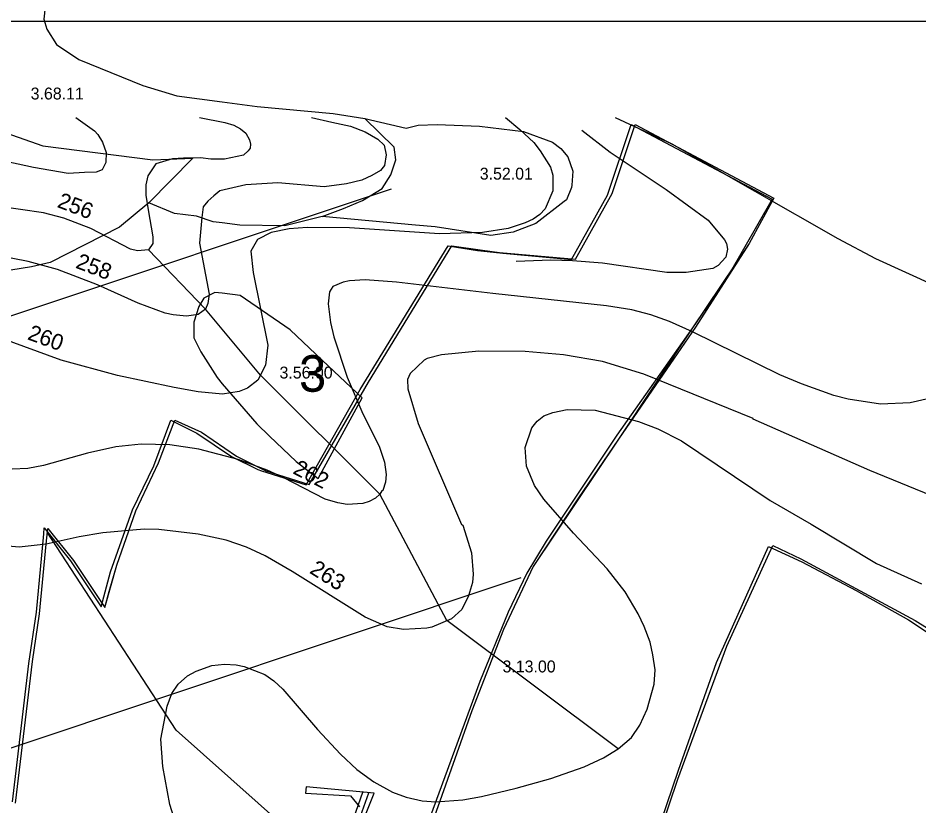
# Model space of a CAD drawing. Extents: x -662500 to -653478, y -1056827 to -1049993.
# Drawn here: x -660129 to -659561, y -1051447 to -1050951 of the extents above; entities that cross this region are included whole.
import ezdxf

# ---------------------------------------------------------------- set-up
doc = ezdxf.new("R2010")
doc.units = 0
for name, color, linetype in [('58', 7, 'Continuous'), ('Vrstva 1', 7, 'Continuous'), ('Vrstva 12', 7, 'Continuous'), ('Vrstva 15', 7, 'Continuous'), ('Vrstva 24', 7, 'Continuous'), ('Vrstva 46', 7, 'Continuous'), ('Vrstva 47', 7, 'Continuous'), ('Vrstva 5', 7, 'Continuous'), ('Vrstva 57', 7, 'Continuous'), ('Vrstva 61', 7, 'Continuous'), ('Vrstva 7', 7, 'Continuous'), ('Vrstva 9', 7, 'Continuous')]:
    doc.layers.add(name, color=color, linetype=linetype)

msp = doc.modelspace()

# ---------------------------------------------------------------- linework, layer by layer
at = {"layer": '58'}
for points in [[(-660132.24, -1051444.58), (-660121.99, -1051357.39), (-660117.08, -1051324.93), (-660112.54, -1051275.65), (-660112.18, -1051271.81), (-660095.7, -1051292.7), (-660076.32, -1051321.57), (-660070.35, -1051299.6), (-660056.66, -1051260.6), (-660043.22, -1051232.73), (-660032.52, -1051204.03), (-660015.99, -1051212.13), (-659994.21, -1051226.93), (-659977.64, -1051235.19), (-659975.32, -1051235.92), (-659947.13, -1051244.87), (-659913.18, -1051184.68), (-659857.71, -1051094.13), (-659839.05, -1051097.05), (-659823.12, -1051098.76), (-659779.88, -1051102.74), (-659757.26, -1051062.21), (-659742.38, -1051017.87), (-659695.85, -1051042.42), (-659653.55, -1051064.75), (-659680.53, -1051112.07), (-659703.59, -1051145.9), (-659751.4, -1051213.59), (-659795.85, -1051280.28), (-659808.05, -1051300.49), (-659819.9, -1051325.04), (-659837.72, -1051368.71), (-659869.54, -1051455.64)], [(-659759.05, -1051561.67), (-659712.51, -1051424.5), (-659688.44, -1051356.77), (-659655.81, -1051283.68), (-659634.82, -1051293.28), (-659600.6, -1051311.32), (-659567.44, -1051329.85), (-659545.76, -1051344.32), (-659531.38, -1051355.46), (-659520.03, -1051370.23), (-659502.95, -1051403.94), (-659485.94, -1051436.16), (-659472.84, -1051453.09)]]:
    msp.add_lwpolyline(points, dxfattribs=at)
at = {"layer": 'Vrstva 1'}
for points in [[(-660130.33, -1051445.37), (-660119.59, -1051356), (-660115.2, -1051326.09), (-660111.07, -1051282.11), (-660109.84, -1051272.31), (-660093.66, -1051292.38), (-660074.1, -1051322.03), (-660071.2, -1051311.9), (-660066.47, -1051295.41), (-660054.39, -1051261.14), (-660040.25, -1051230.96), (-660029.86, -1051204.12), (-660013.02, -1051211.57), (-659991.09, -1051226.64), (-659972.65, -1051235.92), (-659945.31, -1051244.62), (-659907.77, -1051180.02), (-659855.25, -1051094.11), (-659835.96, -1051096.88), (-659825.34, -1051098.5), (-659777.47, -1051102.56), (-659754.32, -1051061.32), (-659739.86, -1051017.86), (-659652.45, -1051064.24)], [(-659652.45, -1051064.24), (-659668.02, -1051092.7), (-659701.79, -1051145.35), (-659750.22, -1051216.02), (-659775.49, -1051252.9), (-659804.11, -1051296.33), (-659822.86, -1051335.88), (-659842.66, -1051387.23), (-659885.47, -1051507.41)], [(-659757.26, -1051561.49), (-659712.92, -1051430.24), (-659682.02, -1051346.44), (-659653.09, -1051282.92), (-659635.47, -1051291.43), (-659563.33, -1051330.24), (-659543.44, -1051342.71), (-659530.33, -1051353.77), (-659518.69, -1051369.3), (-659481.35, -1051440), (-659464.55, -1051461.63)]]:
    msp.add_lwpolyline(points, dxfattribs=at)
at = {"layer": 'Vrstva 12'}
msp.add_lwpolyline([(-660048.46, -1051908.46), (-660047.42, -1051899.64), (-660032.86, -1051840.77), (-660015.78, -1051767.82), (-659988.42, -1051674.38), (-659968.73, -1051615.68), (-659955.2, -1051573.56), (-659924.48, -1051485.89), (-659907.54, -1051438.82)], dxfattribs=at)
at = {"layer": 'Vrstva 15'}
msp.add_lwpolyline([(-659562.5, -1051644.38), (-659615.17, -1051617.96), (-659839.2, -1051534.06), (-659887.53, -1051509.79), (-659927, -1051486.15), (-659960.24, -1051460.73), (-660029.15, -1051399.28), (-660110.36, -1051274.6)], dxfattribs=at)
at = {"layer": 'Vrstva 24'}
for points in [[(-660087.8, -1050870.78), (-660098.95, -1050896.66), (-660106.11, -1050926.12), (-660111.62, -1050943.74), (-660112.44, -1050951.45), (-660110.52, -1050957.79), (-660104.46, -1050967.42), (-660090.42, -1050976.78), (-660050.08, -1050993.3), (-660028.6, -1050999.64), (-660000, -1051003.52), (-659977.94, -1051006.52), (-659930.03, -1051010.93), (-659910.06, -1051013.96)], [(-660219.08, -1051033.89), (-660211.53, -1051026.06), (-660187.02, -1051017.8), (-660160.45, -1051014.5), (-660148.34, -1051016.15), (-660136.5, -1051023.04), (-660113.09, -1051031.3), (-660043.71, -1051040.11), (-660018.65, -1051039.01), (-660046.3, -1051067.21)], [(-659937.05, -1051075.63), (-659923.56, -1051070.68), (-659911.72, -1051065.72), (-659899.33, -1051058.01), (-659893.82, -1051049.48), (-659890.52, -1051040.11), (-659891.62, -1051032.13), (-659910.06, -1051013.96)], [(-659910.06, -1051013.96), (-659884.18, -1051020.01), (-659876.47, -1051018.09), (-659864.63, -1051017.81), (-659837.92, -1051018.91), (-659810.11, -1051022.22), (-659791.94, -1051028.82), (-659786.71, -1051032.95), (-659782.3, -1051038.19), (-659779, -1051047.27), (-659779.7, -1051055.94), (-659779.83, -1051057.46), (-659783.13, -1051065.17), (-659784.51, -1051066.24), (-659802.4, -1051080.04), (-659813.99, -1051084.49), (-659816.72, -1051085.55), (-659830.76, -1051087.75), (-659865.73, -1051082.24), (-659878.14, -1051081.09), (-659937.05, -1051075.63)], [(-660046.3, -1051067.21), (-660064.75, -1051082.36), (-660108.39, -1051104.66), (-660120.23, -1051107.41), (-660153, -1051112.64), (-660174.75, -1051114.57), (-660185.22, -1051114.3), (-660198.16, -1051112.92), (-660298.25, -1051096.4), (-660311.46, -1051099.15), (-660354.83, -1051095.85), (-660390.35, -1051091.17), (-660414.86, -1051087.04), (-660442.11, -1051080.15)], [(-659937.05, -1051075.63), (-659960.67, -1051081.53), (-659989.03, -1051081.25), (-660000, -1051079.82), (-660005.83, -1051079.05), (-660016.29, -1051075.47), (-660030.06, -1051073.82), (-660046.3, -1051067.21)]]:
    msp.add_lwpolyline(points, dxfattribs=at)
msp.add_lwpolyline([(-659932.99, -1051170.05), (-659957.29, -1051147.22), (-659988.68, -1051125.47), (-660000, -1051124.1), (-660004.65, -1051123.54), (-660011.53, -1051127.12), (-660014.83, -1051132.36), (-660017.86, -1051142.27), (-660017.86, -1051152.18), (-660013.46, -1051160.99), (-660003.27, -1051177.24), (-660000, -1051181.05), (-659978.21, -1051206.42), (-659970.15, -1051214.13), (-659953.43, -1051230.1), (-659939.66, -1051240.84), (-659911.85, -1051189.9)], close=True, dxfattribs=at)
at = {"layer": 'Vrstva 46'}
msp.add_line((-659811.8, -1051303.28), (-660954.84, -1051684.73), dxfattribs=at)
at = {"layer": 'Vrstva 47'}
msp.add_line((-659893.49, -1051058.49), (-661206.18, -1051496.55), dxfattribs=at)
at = {"layer": 'Vrstva 5'}
for points in [[(-660130.33, -1051445.37), (-660119.59, -1051356), (-660115.2, -1051326.09), (-660111.07, -1051282.11), (-660109.84, -1051272.31), (-660093.66, -1051292.38), (-660074.1, -1051322.03), (-660066.47, -1051295.41), (-660054.39, -1051261.14), (-660040.25, -1051230.96), (-660029.86, -1051204.12), (-660013.02, -1051211.57), (-659991.09, -1051226.64), (-659972.65, -1051235.92), (-659945.31, -1051244.62), (-659907.77, -1051180.02), (-659855.25, -1051094.11), (-659839.05, -1051097.05), (-659823.12, -1051098.76), (-659777.47, -1051102.56), (-659754.32, -1051061.32), (-659739.86, -1051017.86), (-659652.45, -1051064.24), (-659668.02, -1051092.7), (-659703.59, -1051145.9), (-659750.22, -1051216.02), (-659804.11, -1051296.33), (-659822.86, -1051335.88), (-659842.66, -1051387.23), (-659885.47, -1051507.41)], [(-659757.26, -1051561.49), (-659712.92, -1051430.24), (-659682.02, -1051346.44), (-659653.09, -1051282.92), (-659635.47, -1051291.43), (-659563.33, -1051330.24), (-659543.44, -1051342.71), (-659530.33, -1051353.77), (-659518.69, -1051369.3), (-659481.35, -1051440), (-659465.8, -1051460.02)], [(-659918.03, -1051473.14), (-659904.24, -1051439.07), (-659947.03, -1051435.14), (-659947.53, -1051439.05), (-659919.21, -1051440.8), (-659913.52, -1051447.73)], [(-659918.03, -1051473.14), (-659904.24, -1051439.07), (-659947.03, -1051435.14), (-659947.53, -1051439.05), (-659919.21, -1051440.8), (-659913.52, -1051447.73)]]:
    msp.add_lwpolyline(points, dxfattribs=at)
at = {"layer": 'Vrstva 57'}
msp.add_lwpolyline([(-659750.52, -1051411.12), (-659858.38, -1051330.25), (-659900.74, -1051250.7), (-659975.87, -1051175.63), (-660010.57, -1051134.21), (-660046.43, -1051096.79)], dxfattribs=at)
at = {"layer": 'Vrstva 61'}
msp.add_lwpolyline([(-660053.31, -1051904.2), (-660025.6, -1051792.04), (-660019.11, -1051765.78), (-659991.11, -1051673.25), (-659961.11, -1051581.14), (-659935.76, -1051508.2), (-659911.26, -1051437.7)], dxfattribs=at)
at = {"layer": 'Vrstva 7'}
for p, q in [((-660092.22, -1051013.4), (-660080.42, -1051021.78)), ((-660014.31, -1051013.4), (-659998.39, -1051016.58)), ((-659998.39, -1051016.58), (-659992.72, -1051018.28)), ((-659943.75, -1051013.4), (-659930.93, -1051016.3)), ((-659930.93, -1051016.3), (-659919.28, -1051018.82)), ((-659821.48, -1051013.4), (-659812.45, -1051020.83)), ((-659752.39, -1051013.4), (-659716.65, -1051030.04)), ((-660080.42, -1051021.78), (-660078.44, -1051024.05)), ((-659992.72, -1051018.28), (-659988.46, -1051020.41)), ((-659988.46, -1051020.41), (-659985.06, -1051023.24)), ((-659919.28, -1051018.82), (-659909.95, -1051022.41)), ((-659909.95, -1051022.41), (-659902.06, -1051027.08)), ((-659812.45, -1051020.83), (-659803.67, -1051029.2)), ((-659773.48, -1051021.26), (-659755.48, -1051035.29)), ((-660078.44, -1051024.05), (-660075.48, -1051028.91)), ((-659985.06, -1051023.24), (-659982.8, -1051027.35)), ((-659982.8, -1051027.35), (-659982.23, -1051030.19)), ((-659902.06, -1051027.08), (-659897.97, -1051030.85)), ((-660075.48, -1051028.91), (-660073.1, -1051035.33)), ((-659982.51, -1051032.6), (-659983.65, -1051034.44)), ((-659982.23, -1051030.19), (-659982.51, -1051032.6)), ((-659897.97, -1051030.85), (-659896.69, -1051036.8)), ((-659803.67, -1051029.2), (-659799.7, -1051034.3)), ((-659716.65, -1051030.04), (-659612.07, -1051089.57)), ((-660073.1, -1051035.33), (-660073.46, -1051041.79)), ((-660031.42, -1051039.44), (-660041.89, -1051042.52)), ((-660024.44, -1051038.94), (-660031.42, -1051039.44)), ((-660013.66, -1051038.8), (-660024.44, -1051038.94)), ((-660007.17, -1051039.54), (-660013.66, -1051038.8)), ((-659986.62, -1051036.99), (-659998.67, -1051039.54)), ((-659983.65, -1051034.44), (-659986.62, -1051036.99)), ((-659896.69, -1051036.8), (-659897.75, -1051043.59)), ((-659799.7, -1051034.3), (-659793.18, -1051044.64)), ((-659755.48, -1051035.29), (-659720.34, -1051058.67)), ((-660118.91, -1051044.87), (-660141.52, -1051040.11)), ((-660097.17, -1051048.68), (-660118.91, -1051044.87)), ((-660073.46, -1051041.79), (-660075.74, -1051046.34)), ((-660041.89, -1051042.52), (-660046.9, -1051050.01)), ((-659998.67, -1051039.54), (-660007.17, -1051039.54)), ((-659897.75, -1051043.59), (-659900.26, -1051046.82)), ((-659793.18, -1051044.64), (-659791.76, -1051049.74)), ((-660086.74, -1051048.09), (-660097.17, -1051048.68)), ((-660079.56, -1051047.9), (-660086.74, -1051048.09)), ((-660075.74, -1051046.34), (-660079.56, -1051047.9)), ((-660046.9, -1051050.01), (-660048.26, -1051055.74)), ((-659905.69, -1051049.95), (-659912.15, -1051052.82)), ((-659900.26, -1051046.82), (-659905.69, -1051049.95)), ((-659791.76, -1051049.74), (-659791.62, -1051059.66)), ((-660048.26, -1051055.74), (-660048.26, -1051062.26)), ((-659985.22, -1051055.74), (-660001.53, -1051059.55)), ((-659964.94, -1051054.42), (-659985.22, -1051055.74)), ((-659935.75, -1051056.97), (-659964.94, -1051054.42)), ((-659921.79, -1051055.08), (-659935.75, -1051056.97)), ((-659912.15, -1051052.82), (-659921.79, -1051055.08)), ((-660001.53, -1051059.55), (-660005.33, -1051062.81)), ((-659791.62, -1051059.66), (-659796.58, -1051070.86)), ((-659720.34, -1051058.67), (-659693.7, -1051077.95)), ((-660048.26, -1051062.26), (-660046.63, -1051071.5)), ((-660009.13, -1051066.07), (-660011.95, -1051069.57)), ((-660005.33, -1051062.81), (-660009.13, -1051066.07)), ((-660112.61, -1051073.41), (-660146.05, -1051068.59)), ((-660099.85, -1051076.81), (-660112.61, -1051073.41)), ((-660046.63, -1051071.5), (-660043.73, -1051088.57)), ((-660011.95, -1051069.57), (-660012.8, -1051076.37)), ((-659796.58, -1051070.86), (-659799.84, -1051074.4)), ((-660082.85, -1051083.33), (-660099.85, -1051076.81)), ((-660012.8, -1051076.37), (-660014.26, -1051092.54)), ((-659804.09, -1051077.38), (-659809.05, -1051079.65)), ((-659799.84, -1051074.4), (-659804.09, -1051077.38)), ((-659693.7, -1051077.95), (-659683.49, -1051090.42)), ((-660057.91, -1051096.23), (-660082.85, -1051083.33)), ((-659957.85, -1051083.47), (-659969.19, -1051085.74)), ((-659946.52, -1051082.76), (-659957.85, -1051083.47)), ((-659919.88, -1051082.91), (-659946.52, -1051082.76)), ((-659863.19, -1051086.73), (-659919.88, -1051082.91)), ((-659819.82, -1051083.19), (-659835.98, -1051085.74)), ((-659809.05, -1051079.65), (-659819.82, -1051083.19)), ((-660043.73, -1051088.57), (-660043.73, -1051092.68)), ((-659977.7, -1051090.13), (-659982.09, -1051097.64)), ((-659969.19, -1051085.74), (-659977.7, -1051090.13)), ((-659835.98, -1051085.74), (-659863.19, -1051086.73)), ((-659683.49, -1051090.42), (-659682.22, -1051092.83)), ((-659612.07, -1051089.57), (-659588.26, -1051102.18)), ((-660053.37, -1051097.36), (-660057.91, -1051096.23)), ((-660043.73, -1051092.68), (-660046.43, -1051096.79)), ((-660014.26, -1051092.54), (-660008.16, -1051124.57)), ((-659681.51, -1051096.23), (-659682.64, -1051101.33)), ((-659682.22, -1051092.83), (-659681.51, -1051096.23)), ((-660122.25, -1051104.02), (-660143.5, -1051100.05)), ((-660046.43, -1051096.79), (-660053.37, -1051097.36)), ((-659982.09, -1051097.64), (-659980.53, -1051110.97)), ((-659682.64, -1051101.33), (-659687.46, -1051106.57)), ((-660103.82, -1051109.12), (-660122.25, -1051104.02)), ((-659792.9, -1051103.31), (-659814.86, -1051104.16)), ((-659779.29, -1051103.6), (-659792.9, -1051103.31)), ((-659760.3, -1051105.16), (-659779.29, -1051103.6)), ((-659719.91, -1051110.97), (-659760.3, -1051105.16)), ((-659687.46, -1051106.57), (-659690.86, -1051108.42)), ((-659588.26, -1051102.18), (-659550.56, -1051119.47)), ((-660078.6, -1051118.76), (-660103.82, -1051109.12)), ((-659980.53, -1051110.97), (-659971.32, -1051156.88)), ((-659707.58, -1051110.97), (-659719.91, -1051110.97)), ((-659690.86, -1051108.42), (-659707.58, -1051110.97)), ((-660053.09, -1051130.24), (-660078.6, -1051118.76)), ((-659923.84, -1051117.06), (-659930.22, -1051119.89)), ((-659919.88, -1051116.21), (-659923.84, -1051117.06)), ((-659909.95, -1051115.64), (-659919.88, -1051116.21)), ((-659890.11, -1051117.06), (-659909.95, -1051115.64)), ((-659829.46, -1051124.29), (-659890.11, -1051117.06)), ((-660008.16, -1051124.57), (-660009.01, -1051130.52)), ((-659932.49, -1051123.29), (-659933.34, -1051130.81)), ((-659930.22, -1051119.89), (-659932.49, -1051123.29)), ((-659757.75, -1051131.94), (-659829.46, -1051124.29)), ((-660036.08, -1051136.62), (-660053.09, -1051130.24)), ((-660010.57, -1051134.21), (-660015.11, -1051137.47)), ((-660009.01, -1051130.52), (-660010.57, -1051134.21)), ((-659933.34, -1051130.81), (-659931.78, -1051142.43)), ((-659741.88, -1051134.63), (-659757.75, -1051131.94)), ((-659729.97, -1051137.61), (-659741.88, -1051134.63)), ((-660030.98, -1051137.75), (-660036.08, -1051136.62)), ((-660022.48, -1051138.46), (-660030.98, -1051137.75)), ((-660015.11, -1051137.47), (-660022.48, -1051138.46)), ((-659718.07, -1051141.86), (-659729.97, -1051137.61)), ((-659931.78, -1051142.43), (-659929.65, -1051151.5)), ((-659703.61, -1051148.38), (-659718.07, -1051141.86)), ((-660101.56, -1051166.24), (-660140.1, -1051152.21)), ((-659929.65, -1051151.5), (-659921.29, -1051177.01)), ((-659648.63, -1051175.45), (-659703.61, -1051148.38)), ((-659971.32, -1051156.88), (-659972.73, -1051169.35)), ((-659861.77, -1051162.98), (-659870.84, -1051165.24)), ((-659838.25, -1051160.57), (-659861.77, -1051162.98)), ((-659809.05, -1051160.85), (-659838.25, -1051160.57)), ((-659784.96, -1051162.83), (-659809.05, -1051160.85)), ((-659760.44, -1051167.08), (-659784.96, -1051162.83)), ((-660066.13, -1051175.87), (-660101.56, -1051166.24)), ((-659972.73, -1051169.35), (-659977.55, -1051178.85)), ((-659872.68, -1051166.24), (-659881.61, -1051174.6)), ((-659870.84, -1051165.24), (-659872.68, -1051166.24)), ((-659734.23, -1051175.16), (-659760.44, -1051167.08)), ((-659881.61, -1051174.6), (-659883.31, -1051178.42)), ((-659665.49, -1051202.94), (-659734.23, -1051175.16)), ((-659635.03, -1051181.11), (-659648.63, -1051175.45)), ((-660030.41, -1051183.52), (-660066.13, -1051175.87)), ((-659977.55, -1051178.85), (-659984.07, -1051183.81)), ((-659921.29, -1051177.01), (-659911.51, -1051199.96)), ((-659883.31, -1051178.42), (-659883.03, -1051184.38)), ((-659614.62, -1051188.48), (-659635.03, -1051181.11)), ((-660015.11, -1051186.22), (-660030.41, -1051183.52)), ((-659999.8, -1051187.63), (-660015.11, -1051186.22)), ((-659989.32, -1051186.07), (-659999.8, -1051187.63)), ((-659984.07, -1051183.81), (-659989.32, -1051186.07)), ((-659883.03, -1051184.38), (-659876.51, -1051206.2)), ((-659605.55, -1051190.89), (-659614.62, -1051188.48)), ((-659585.14, -1051194.01), (-659605.55, -1051190.89)), ((-659554.53, -1051190.33), (-659566.43, -1051193.16)), ((-659791.76, -1051199.11), (-659782.69, -1051197.41)), ((-659782.69, -1051197.41), (-659764.98, -1051197.7)), ((-659764.98, -1051197.7), (-659737.63, -1051204.78)), ((-659566.43, -1051193.16), (-659585.14, -1051194.01)), ((-659911.51, -1051199.96), (-659901.17, -1051220.37)), ((-659801.54, -1051204.64), (-659797.43, -1051201.38)), ((-659797.43, -1051201.38), (-659791.76, -1051199.11)), ((-659665.35, -1051203.51), (-659665.49, -1051202.94)), ((-659591.94, -1051235.82), (-659665.35, -1051203.51)), ((-659876.51, -1051206.2), (-659849.16, -1051269.69)), ((-659809.19, -1051221.22), (-659804.94, -1051208.89)), ((-659804.94, -1051208.89), (-659801.54, -1051204.64)), ((-659737.63, -1051204.78), (-659725.44, -1051209.6)), ((-659725.44, -1051209.6), (-659710.56, -1051217.11)), ((-660066.98, -1051220.8), (-660084.83, -1051224.76)), ((-660051.1, -1051219.09), (-660066.98, -1051220.8)), ((-660032.96, -1051219.52), (-660051.1, -1051219.09)), ((-660014.83, -1051222.35), (-660032.96, -1051219.52)), ((-659901.17, -1051220.37), (-659897.77, -1051230.57)), ((-659710.56, -1051217.11), (-659654.72, -1051254.67)), ((-660084.83, -1051224.76), (-660112.61, -1051232.7)), ((-659989.88, -1051228.87), (-660014.83, -1051222.35)), ((-659808.34, -1051233.12), (-659809.19, -1051221.22)), ((-659971.74, -1051235.53), (-659989.88, -1051228.87)), ((-659897.77, -1051230.57), (-659896.63, -1051238.23)), ((-660122.53, -1051234.54), (-660132.45, -1051234.97)), ((-660112.61, -1051232.7), (-660122.53, -1051234.54)), ((-659961.68, -1051240.07), (-659971.74, -1051235.53)), ((-659896.63, -1051238.23), (-659897.2, -1051243.04)), ((-659803.24, -1051245.31), (-659808.34, -1051233.12)), ((-659548.15, -1051253.67), (-659591.94, -1051235.82)), ((-659935.18, -1051253.82), (-659961.68, -1051240.07)), ((-659897.2, -1051243.04), (-659898.76, -1051248.43)), ((-659899.47, -1051248.57), (-659900.74, -1051250.7)), ((-659898.76, -1051248.43), (-659899.47, -1051248.57)), ((-659797.43, -1051253.82), (-659803.24, -1051245.31)), ((-659927.24, -1051256.23), (-659935.18, -1051253.82)), ((-659903.44, -1051253.11), (-659907.4, -1051255.38)), ((-659900.74, -1051250.7), (-659903.44, -1051253.11)), ((-659778.72, -1051275.22), (-659797.43, -1051253.82)), ((-659654.72, -1051254.67), (-659628.79, -1051269.55)), ((-659921.29, -1051257.22), (-659927.24, -1051256.23)), ((-659911.37, -1051256.65), (-659921.29, -1051257.22)), ((-659907.4, -1051255.38), (-659911.37, -1051256.65)), ((-659849.16, -1051269.69), (-659848.45, -1051270.26)), ((-659848.45, -1051270.26), (-659842.92, -1051287.54)), ((-659628.79, -1051269.55), (-659587.69, -1051294.35)), ((-660090.22, -1051277.48), (-660110.91, -1051282.16)), ((-660075.2, -1051275.07), (-660090.22, -1051277.48)), ((-660049.12, -1051272.66), (-660075.2, -1051275.07)), ((-660040.05, -1051272.95), (-660049.12, -1051272.66)), ((-660015.25, -1051275.78), (-660040.05, -1051272.95)), ((-659997.54, -1051279.61), (-660015.25, -1051275.78)), ((-659757.33, -1051297.61), (-659778.72, -1051275.22)), ((-660127.91, -1051284), (-660176.67, -1051279.89)), ((-660110.91, -1051282.16), (-660127.91, -1051284)), ((-659984.64, -1051284.14), (-659997.54, -1051279.61)), ((-659972.88, -1051289.53), (-659984.64, -1051284.14)), ((-659842.92, -1051287.54), (-659841.79, -1051301.15)), ((-659955.87, -1051299.45), (-659972.88, -1051289.53)), ((-659587.69, -1051294.35), (-659559.35, -1051307.1)), ((-659909.95, -1051328.22), (-659955.87, -1051299.45)), ((-659746.13, -1051312.2), (-659757.33, -1051297.61)), ((-659842.21, -1051306.25), (-659844.77, -1051314.75)), ((-659841.79, -1051301.15), (-659842.21, -1051306.25)), ((-659844.77, -1051314.75), (-659849.02, -1051323.26)), ((-659737.91, -1051326.09), (-659746.13, -1051312.2)), ((-659849.02, -1051323.26), (-659855.54, -1051329.21)), ((-659896.07, -1051334.17), (-659909.95, -1051328.22)), ((-659734.08, -1051334.03), (-659737.91, -1051326.09)), ((-659885.86, -1051336.01), (-659896.07, -1051334.17)), ((-659868.01, -1051334.45), (-659871.12, -1051335.16)), ((-659855.54, -1051329.21), (-659868.01, -1051334.45)), ((-659730.4, -1051343.95), (-659734.08, -1051334.03)), ((-659871.12, -1051335.16), (-659885.86, -1051336.01)), ((-659728.56, -1051351.88), (-659730.4, -1051343.95)), ((-659727.28, -1051361.38), (-659728.56, -1051351.88)), ((-660021.91, -1051365.21), (-660016.53, -1051362.09)), ((-660016.53, -1051362.09), (-660006.6, -1051358.69)), ((-660006.6, -1051358.69), (-659998.67, -1051357.84)), ((-659998.67, -1051357.84), (-659991.3, -1051358.12)), ((-659991.3, -1051358.12), (-659986.2, -1051359.25)), ((-659986.2, -1051359.25), (-659973.16, -1051364.21)), ((-659727.85, -1051370.31), (-659727.28, -1051361.38)), ((-660027.72, -1051370.45), (-660021.91, -1051365.21)), ((-659973.16, -1051364.21), (-659967.49, -1051368.32)), ((-659967.49, -1051368.32), (-659961.82, -1051373.57)), ((-660031.69, -1051376.26), (-660027.72, -1051370.45)), ((-659961.82, -1051373.57), (-659940, -1051398.93)), ((-659732.24, -1051386.18), (-659727.85, -1051370.31)), ((-660034.67, -1051384.2), (-660031.69, -1051376.26)), ((-660038.63, -1051405.03), (-660034.67, -1051384.2)), ((-659736.78, -1051396.1), (-659732.24, -1051386.18)), ((-659742.16, -1051403.89), (-659736.78, -1051396.1)), ((-659940, -1051398.93), (-659925.4, -1051414.52)), ((-660037.5, -1051422.18), (-660038.63, -1051405.03)), ((-659750.52, -1051411.12), (-659742.16, -1051403.89)), ((-659759.73, -1051416.79), (-659750.52, -1051411.12)), ((-659925.4, -1051414.52), (-659915.2, -1051424.16)), ((-659771.92, -1051422.46), (-659759.73, -1051416.79)), ((-660032.96, -1051446.27), (-660037.5, -1051422.18)), ((-659915.2, -1051424.16), (-659904.57, -1051431.95)), ((-659792.9, -1051429.83), (-659771.92, -1051422.46)), ((-659814.72, -1051435.92), (-659792.9, -1051429.83)), ((-659904.57, -1051431.95), (-659892.67, -1051438.33)), ((-659836.55, -1051441.17), (-659814.72, -1051435.92)), ((-659892.67, -1051438.33), (-659884.16, -1051441.59)), ((-659884.16, -1051441.59), (-659873.96, -1051443.86)), ((-659848.45, -1051443.29), (-659836.55, -1051441.17)), ((-660028.57, -1051460.44), (-660032.96, -1051446.27)), ((-659873.96, -1051443.86), (-659865.46, -1051444.57)), ((-659865.46, -1051444.57), (-659848.45, -1051443.29))]:
    msp.add_line(p, q, dxfattribs=at)
at = {"layer": 'Vrstva 9'}
msp.add_line((-657221.63, -1050952.96), (-661971.63, -1050952.96), dxfattribs=at)

# ---------------------------------------------------------------- texts
at = {"layer": 'Vrstva 24'}
for s, p in [('3.68.11', (-660120.74, -1051002.02)), ('3.52.01', (-659837.71, -1051052.49)), ('3.56.00', (-659963.92, -1051177.81)), ('3.13.00', (-659823.38, -1051362.96))]:
    msp.add_text(s, height=7.5, dxfattribs=at).set_placement(p)
at = {"layer": 'Vrstva 57'}
msp.add_text('3', height=23, dxfattribs=at).set_placement((-659951.61, -1051186.15))
at = {"layer": 'Vrstva 7'}
for s, rotation, p in [('256', 339.0264, (-660104.59, -1051069.64)), ('258', 339.0918, (-660092.96, -1051107.92)), ('260', 339.9999, (-660123.28, -1051153)), ('262', 332.5826, (-659956.06, -1051237.35)), ('263', 327.9311, (-659945.54, -1051300.02))]:
    msp.add_text(s, height=10, rotation=rotation, dxfattribs=at).set_placement(p)

doc.saveas('drawing.dxf')
